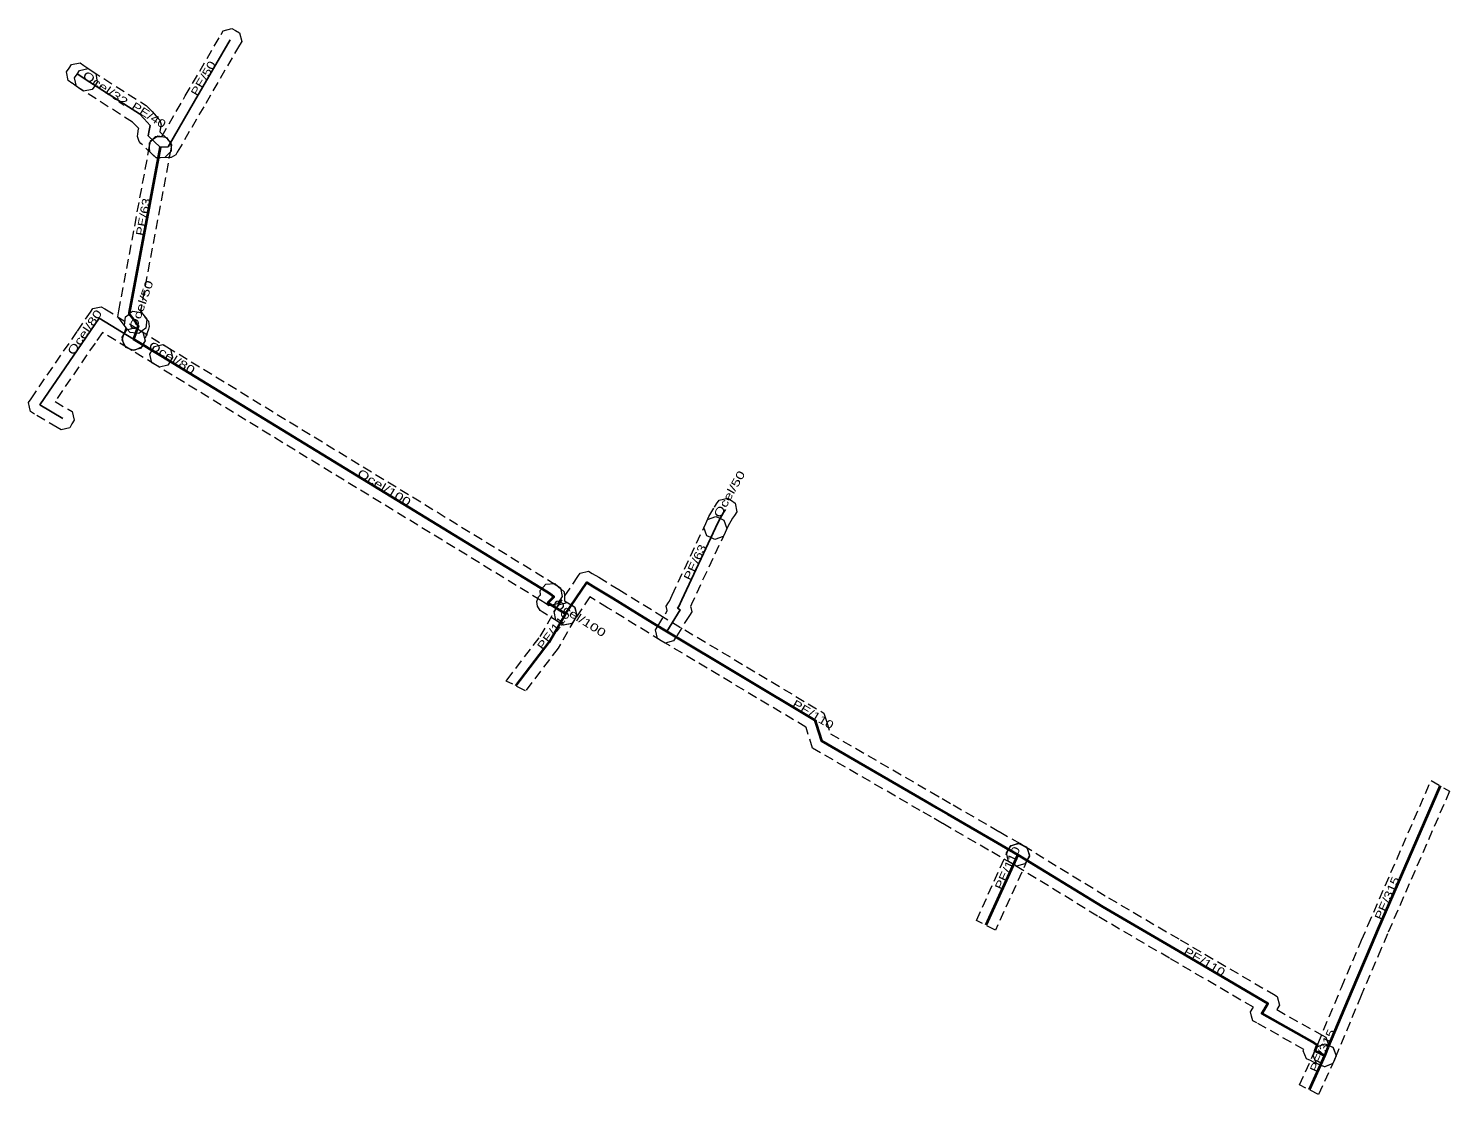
# Model space of a CAD drawing. Extents: x -482856 to -482723, y -1127129 to -1127029.
import ezdxf

# ---------------------------------------------------------------- set-up
doc = ezdxf.new("R2010")
doc.units = 0
doc.header["$LTSCALE"] = 0.3
doc.linetypes.add('MEDIUM_DASHED', pattern=[4.5, 3, -1.5])
doc.layers.add('1', color=7, linetype='MEDIUM_DASHED', lineweight=13)
doc.layers.add('14', color=7, linetype='Continuous', lineweight=40)
doc.layers.add('20', color=7, linetype='Continuous')

msp = doc.modelspace()

# ---------------------------------------------------------------- linework, layer by layer
at = {"layer": '1'}
for points in [[(-482844.196, -1127039.548), (-482843.782, -1127039.539), (-482843.617, -1127039.536), (-482841.411, -1127035.744), (-482838.065, -1127029.987), (-482837.857, -1127029.629), (-482837.055, -1127029.417), (-482836.697, -1127029.625), (-482836.339, -1127029.833), (-482836.127, -1127030.635), (-482836.335, -1127030.993), (-482839.683, -1127036.75), (-482842.17, -1127041.026), (-482842.301, -1127041.251), (-482842.751, -1127041.517), (-482843.012, -1127041.523), (-482843.738, -1127041.539), (-482844.152, -1127041.548), (-482844.751, -1127040.975), (-482844.76, -1127040.561), (-482844.769, -1127040.147)], [(-482851.264, -1127032.651), (-482850.923, -1127032.886), (-482850.153, -1127033.416), (-482849.812, -1127033.651), (-482849.661, -1127034.466), (-482849.896, -1127034.807), (-482850.131, -1127035.148), (-482850.946, -1127035.299), (-482851.287, -1127035.064), (-482852.057, -1127034.534), (-482852.398, -1127034.299), (-482852.549, -1127033.484), (-482852.314, -1127033.143), (-482852.079, -1127032.802)], [(-482845.785, -1127038.817), (-482845.783, -1127038.807), (-482845.992, -1127038.572), (-482846.354, -1127038.202), (-482851.257, -1127035.084), (-482851.606, -1127034.862), (-482851.786, -1127034.053), (-482851.564, -1127033.703), (-482851.342, -1127033.354), (-482850.533, -1127033.174), (-482850.183, -1127033.396), (-482845.086, -1127036.638), (-482844.528, -1127037.208), (-482843.962, -1127037.846), (-482843.808, -1127038.02), (-482843.684, -1127038.466), (-482843.727, -1127038.694), (-482843.806, -1127039.112), (-482843.069, -1127039.816), (-482842.77, -1127040.102), (-482842.751, -1127040.931), (-482843.037, -1127041.23), (-482843.323, -1127041.529), (-482844.152, -1127041.548), (-482844.451, -1127041.262), (-482845.57, -1127040.193), (-482845.749, -1127040.022), (-482845.906, -1127039.552), (-482845.866, -1127039.308)], [(-482842.777, -1127040.722), (-482845.614, -1127055.926), (-482845.278, -1127056.353), (-482845.022, -1127056.678), (-482845.119, -1127057.501), (-482845.444, -1127057.757), (-482845.769, -1127058.013), (-482846.592, -1127057.916), (-482846.848, -1127057.591), (-482847.404, -1127056.887), (-482847.745, -1127056.456), (-482847.643, -1127055.899), (-482844.743, -1127040.356), (-482844.667, -1127039.949), (-482843.984, -1127039.48), (-482843.577, -1127039.556), (-482843.17, -1127039.632), (-482842.701, -1127040.315)], [(-482853.053, -1127067.04), (-482853.409, -1127066.829), (-482855.559, -1127065.554), (-482855.932, -1127065.333), (-482856.025, -1127064.91), (-482856.119, -1127064.487), (-482855.874, -1127064.129), (-482851.523, -1127057.776), (-482850.304, -1127055.996), (-482850.079, -1127055.667), (-482849.299, -1127055.5), (-482848.958, -1127055.708), (-482845.737, -1127057.676), (-482845.383, -1127057.892), (-482845.189, -1127058.697), (-482845.405, -1127059.05), (-482845.621, -1127059.404), (-482846.426, -1127059.598), (-482846.779, -1127059.382), (-482849.19, -1127057.909), (-482849.873, -1127058.906), (-482853.621, -1127064.378), (-482852.389, -1127065.109), (-482852.033, -1127065.32), (-482851.828, -1127066.123), (-482852.039, -1127066.479), (-482852.25, -1127066.835)], [(-482847.202, -1127058.198), (-482846.946, -1127057.467), (-482847.105, -1127057.264), (-482847.007, -1127056.442), (-482846.681, -1127056.186), (-482846.355, -1127055.93), (-482845.533, -1127056.028), (-482845.277, -1127056.354), (-482845.16, -1127056.503), (-482845.036, -1127056.66), (-482844.876, -1127056.861), (-482844.791, -1127057.368), (-482844.876, -1127057.611), (-482845.314, -1127058.86), (-482845.451, -1127059.251), (-482846.198, -1127059.61), (-482846.589, -1127059.473), (-482846.98, -1127059.336), (-482847.339, -1127058.589)], [(-482846.09, -1127057.46), (-482845.737, -1127057.676), (-482843.155, -1127059.253), (-482842.801, -1127059.469), (-482842.607, -1127060.274), (-482842.823, -1127060.627), (-482843.039, -1127060.981), (-482843.844, -1127061.175), (-482844.197, -1127060.959), (-482846.779, -1127059.382), (-482847.133, -1127059.166), (-482847.327, -1127058.361), (-482847.111, -1127058.008), (-482846.895, -1127057.654)], [(-482843.508, -1127059.037), (-482843.155, -1127059.253), (-482807.012, -1127081.337), (-482806.575, -1127081.628), (-482806.23, -1127081.858), (-482806.068, -1127082.67), (-482806.298, -1127083.015), (-482806.528, -1127083.36), (-482807.34, -1127083.522), (-482807.685, -1127083.292), (-482808.088, -1127083.023), (-482844.197, -1127060.959), (-482844.551, -1127060.743), (-482844.745, -1127059.938), (-482844.529, -1127059.585), (-482844.313, -1127059.231)], [(-482792.796, -1127076.187), (-482792.62, -1127075.812), (-482792.319, -1127075.17), (-482791.814, -1127074.279), (-482791.606, -1127073.962), (-482791.379, -1127073.616), (-482790.568, -1127073.447), (-482790.222, -1127073.674), (-482789.876, -1127073.901), (-482789.707, -1127074.712), (-482789.934, -1127075.058), (-482790.106, -1127075.321), (-482790.541, -1127076.09), (-482790.81, -1127076.662), (-482790.986, -1127077.037), (-482791.765, -1127077.318), (-482792.14, -1127077.142), (-482792.515, -1127076.966)], [(-482797.121, -1127085.425), (-482796.239, -1127083.997), (-482796.245, -1127083.971), (-482796.338, -1127083.56), (-482796.11, -1127083.207), (-482796.037, -1127083.094), (-482795.776, -1127082.539), (-482792.62, -1127075.812), (-482792.444, -1127075.437), (-482791.665, -1127075.156), (-482791.29, -1127075.332), (-482790.915, -1127075.508), (-482790.634, -1127076.287), (-482790.81, -1127076.662), (-482793.966, -1127083.387), (-482794.059, -1127083.586), (-482794.037, -1127083.679), (-482793.941, -1127084.083), (-482794.159, -1127084.435), (-482795.419, -1127086.475), (-482795.637, -1127086.827), (-482796.443, -1127087.018), (-482796.795, -1127086.801), (-482797.147, -1127086.583), (-482797.338, -1127085.777)], [(-482801.827, -1127083.713), (-482803.484, -1127082.697), (-482804.942, -1127084.851), (-482805.174, -1127085.194), (-482805.988, -1127085.35), (-482806.331, -1127085.118), (-482806.674, -1127084.886), (-482806.83, -1127084.072), (-482806.598, -1127083.729), (-482804.608, -1127080.789), (-482804.385, -1127080.459), (-482803.607, -1127080.288), (-482803.266, -1127080.493), (-482802.661, -1127080.855), (-482800.781, -1127082.009), (-482796.937, -1127084.368), (-482795.752, -1127085.095), (-482781.551, -1127093.587), (-482781.317, -1127094.328), (-482780.934, -1127095.528), (-482771.507, -1127100.986), (-482770.467, -1127101.596), (-482769.43, -1127102.194), (-482765.109, -1127104.694), (-482762.86, -1127105.994), (-482762.501, -1127106.201), (-482762.287, -1127107.001), (-482762.494, -1127107.36), (-482762.701, -1127107.719), (-482763.501, -1127107.933), (-482763.86, -1127107.726), (-482766.111, -1127106.426), (-482770.43, -1127103.926), (-482771.473, -1127103.324), (-482772.513, -1127102.714), (-482782.606, -1127096.872), (-482783.223, -1127094.932), (-482783.229, -1127094.913), (-482796.788, -1127086.805), (-482797.983, -1127086.072)], [(-482808.131, -1127082.527), (-482808.128, -1127082.524), (-482808.154, -1127082.107), (-482807.879, -1127081.797), (-482807.604, -1127081.487), (-482806.777, -1127081.436), (-482806.467, -1127081.711), (-482806.207, -1127081.941), (-482805.882, -1127082.229), (-482805.87, -1127082.664), (-482805.86, -1127083.05), (-482805.235, -1127083.445), (-482804.885, -1127083.666), (-482804.703, -1127084.475), (-482804.925, -1127084.825), (-482805.146, -1127085.175), (-482805.955, -1127085.357), (-482806.305, -1127085.135), (-482807.965, -1127084.085), (-482808.158, -1127083.963), (-482808.4, -1127083.574), (-482808.424, -1127083.346), (-482808.449, -1127083.118), (-482808.294, -1127082.687)], [(-482806.466, -1127087.505), (-482809.516, -1127091.501), (-482811.32, -1127090.582), (-482811.246, -1127090.47), (-482808.134, -1127086.395), (-482806.637, -1127083.791), (-482806.43, -1127083.432), (-482805.63, -1127083.217), (-482805.271, -1127083.423), (-482804.912, -1127083.63), (-482804.697, -1127084.43), (-482804.903, -1127084.789)], [(-482730.548, -1127113.484), (-482724.629, -1127099.89), (-482722.894, -1127100.916), (-482728.712, -1127114.276), (-482729.3, -1127115.652), (-482731.179, -1127120.069), (-482733.376, -1127125.313), (-482733.675, -1127126.04), (-482733.832, -1127126.423), (-482734.597, -1127126.742), (-482734.98, -1127126.585), (-482735.363, -1127126.428), (-482735.682, -1127125.663), (-482735.525, -1127125.28), (-482735.224, -1127124.547), (-482733.021, -1127119.291), (-482731.14, -1127114.868)], [(-482765.463, -1127113.923), (-482767.248, -1127113.014), (-482764.271, -1127106.447), (-482764.1, -1127106.07), (-482763.324, -1127105.778), (-482762.947, -1127105.949), (-482762.57, -1127106.12), (-482762.278, -1127106.896), (-482762.449, -1127107.273)], [(-482741.337, -1127121.236), (-482741.29, -1127121.157), (-482749.165, -1127116.553), (-482755.904, -1127112.608), (-482763.883, -1127107.712), (-482764.236, -1127107.495), (-482764.429, -1127106.69), (-482764.212, -1127106.337), (-482763.995, -1127105.984), (-482763.19, -1127105.791), (-482762.837, -1127106.008), (-482754.876, -1127110.892), (-482748.155, -1127114.827), (-482739.415, -1127119.937), (-482739.058, -1127120.146), (-482738.848, -1127120.946), (-482739.056, -1127121.304), (-482739.1, -1127121.38), (-482735.063, -1127123.653), (-482734.824, -1127123.786), (-482734.498, -1127123.967), (-482734.243, -1127124.667), (-482734.262, -1127124.717), (-482734.206, -1127124.741), (-482733.825, -1127124.904), (-482733.518, -1127125.673), (-482733.681, -1127126.054), (-482733.844, -1127126.435), (-482734.613, -1127126.742), (-482734.994, -1127126.579), (-482735.215, -1127126.484), (-482735.644, -1127126.288), (-482735.947, -1127126.149), (-482736.305, -1127125.984), (-482736.605, -1127125.254), (-482736.551, -1127125.111), (-482740.971, -1127122.621), (-482741.339, -1127122.414), (-482741.447, -1127122.006), (-482741.555, -1127121.598)], [(-482735.175, -1127129.339), (-482736.959, -1127128.431), (-482735.51, -1127125.246), (-482735.339, -1127124.869), (-482734.563, -1127124.579), (-482734.186, -1127124.75), (-482733.809, -1127124.921), (-482733.519, -1127125.697), (-482733.69, -1127126.074)]]:
    msp.add_lwpolyline(points, close=True, dxfattribs=at)
at = {"layer": '14', "lineweight": 25}
msp.add_line((-482851.49, -1127033.71), (-482850.72, -1127034.24), dxfattribs=at)
at = {"layer": '14'}
for p, q in [((-482846.258, -1127058.529), (-482843.676, -1127060.106)), ((-482763.36, -1127106.86), (-482766.355, -1127113.469)), ((-482734.6, -1127125.66), (-482736.067, -1127128.885))]:
    msp.add_line(p, q, dxfattribs=at)
at = {"layer": '14', "lineweight": 25}
for points in [[(-482843.76, -1127040.539), (-482843.034, -1127040.523), (-482840.547, -1127036.247), (-482837.2, -1127030.49)], [(-482843.76, -1127040.539), (-482844.879, -1127039.47), (-482844.8, -1127038.99), (-482844.71, -1127038.51), (-482845.26, -1127037.89), (-482845.72, -1127037.42), (-482850.72, -1127034.24)], [(-482852.899, -1127065.969), (-482855.049, -1127064.694), (-482850.698, -1127058.341), (-482849.479, -1127056.561), (-482846.258, -1127058.529)], [(-482791.715, -1127076.237), (-482791.43, -1127075.63), (-482790.96, -1127074.8), (-482790.77, -1127074.51)], [(-482796.27, -1127085.95), (-482795.01, -1127083.91), (-482795.27, -1127083.75), (-482795.16, -1127083.58), (-482794.871, -1127082.963), (-482791.715, -1127076.237)]]:
    msp.add_lwpolyline(points, dxfattribs=at)
at = {"layer": '14'}
for points in [[(-482843.76, -1127040.539), (-482846.66, -1127056.08), (-482846.68, -1127056.19), (-482846.619, -1127056.267), (-482846.063, -1127056.972)], [(-482846.063, -1127056.972), (-482845.945, -1127057.122), (-482845.82, -1127057.28), (-482846.258, -1127058.529)], [(-482843.676, -1127060.106), (-482807.55, -1127082.18), (-482807.13, -1127082.46)], [(-482805.77, -1127084.29), (-482803.78, -1127081.35), (-482803.18, -1127081.71), (-482801.304, -1127082.861), (-482798.415, -1127084.633), (-482797.46, -1127085.22), (-482796.27, -1127085.95), (-482782.39, -1127094.25), (-482782.27, -1127094.63), (-482781.77, -1127096.2), (-482772.01, -1127101.85), (-482770.97, -1127102.46), (-482769.93, -1127103.06), (-482765.61, -1127105.56), (-482763.36, -1127106.86)], [(-482807.13, -1127082.46), (-482806.87, -1127082.69), (-482807.43, -1127083.24), (-482805.77, -1127084.29)], [(-482810.422, -1127091.04), (-482807.3, -1127086.95), (-482805.77, -1127084.29)], [(-482723.761, -1127100.403), (-482729.63, -1127113.88), (-482730.22, -1127115.26), (-482732.1, -1127119.68), (-482734.3, -1127124.93), (-482734.6, -1127125.66)], [(-482763.36, -1127106.86), (-482755.39, -1127111.75), (-482748.66, -1127115.69), (-482739.92, -1127120.8), (-482740.27, -1127121.4), (-482740.48, -1127121.75), (-482735.551, -1127124.526), (-482735.357, -1127124.633), (-482735.31, -1127124.66), (-482735.53, -1127125.24), (-482735.227, -1127125.379), (-482734.81, -1127125.57), (-482734.6, -1127125.66)]]:
    msp.add_lwpolyline(points, dxfattribs=at)

# ---------------------------------------------------------------- texts
at = {"layer": '20'}
for s, rotation, width, p in [('PE/50', 59.827, 1.3, (-482840.299, -1127035.82)), ('Ocel/32', 325.46, 1.4, (-482851.105, -1127033.975)), ('PE/40', 327.544, 1.3, (-482846.528, -1127036.905)), ('PE/63', 79.43, 1.3, (-482845.321, -1127048.903)), ('Ocel/50', 70.675, 1.4, (-482845.991, -1127057.766)), ('Ocel/80', 55.594, 1.4, (-482851.904, -1127060.101)), ('Ocel/80', 328.585, 1.4, (-482844.924, -1127059.343)), ('Ocel/100', 328.574, 1.4, (-482825.355, -1127071.3)), ('Ocel/50', 60.479, 1.4, (-482791.275, -1127075.356)), ('PE/63', 64.863, 1.3, (-482794.055, -1127081.223)), ('Ocel/100', 327.685, 1.4, (-482807.036, -1127083.489)), ('PE/110', 52.641, 1.3, (-482807.9, -1127087.735)), ('PE/110', 329.121, 1.3, (-482784.582, -1127092.939)), ('PE/110', 65.617, 1.3, (-482764.879, -1127110.21)), ('PE/315', 66.469, 1.3, (-482729.268, -1127113.048)), ('PE/110', 329.687, 1.3, (-482747.904, -1127116.132)), ('PE/315', 65.535, 1.3, (-482735.354, -1127127.318))]:
    msp.add_text(s, height=0.75, rotation=rotation, dxfattribs=dict(at, width=width)).set_placement(p)

doc.saveas('drawing.dxf')
